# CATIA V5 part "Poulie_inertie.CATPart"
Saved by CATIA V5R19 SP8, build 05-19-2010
Part number: Poulie_inertie
Nomenclature: 69_c
Bounding box of the stored display mesh (mm): x -20 to 42, y -64.996 to 64.996, z -64.996 to 64.996
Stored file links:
  C:\Users\rphgr\Desktop\0_Tapis_TC520B_vitesse\Poulie_inertie.CATPart
  D:\Documents\1_Travail\1 - ac-limoges.fr\ac-limoges.fr\Emmanuel Maynard - STI2D_Turgot\3 - Supports\Tapis de course TC520B\Tapis de course TC520B_Ca\0_Tapis_TC520B.CATProduct
  D:\Documents\1_Travail\1 - ac-limoges.fr\ac-limoges.fr\Emmanuel Maynard - STI2D_Turgot\3 - Supports\Tapis de course TC520B\Tapis de course TC520B_Ca\Rotor.CATPart
  D:\Documents\1_Travail\1 - ac-limoges.fr\ac-limoges.fr\Emmanuel Maynard - STI2D_Turgot\3 - Supports\Tapis de course TC520B\Tapis de course TC520B_Ca\JIS_B_1301_5x5x28_SYMBOL_C_WITHOUT_HOLES_PARALLEL_KEY.CATPart
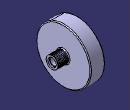
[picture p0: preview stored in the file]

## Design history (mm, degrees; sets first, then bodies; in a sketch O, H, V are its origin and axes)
AxisSystem1: origin (0, 0, 0), X (1, 0, 0), Y (0, 1, 0), Z (0, 0, 1)
Set1
  DatumSurface1 to DatumSurface3
Body1 (main body)
  Sketch1 on ZX plane of AxisSystem1, origin (0, 0, 0), H (0, 0, 1), V (1, 0, 0)
    axis line L1 (0, -2.8084) -> (0, 45.1811)
    point P1 (0, -2.8084)
    line L2 (8, 0) -> (13.25, 0)
    line L3 (13.25, 0) -> (13.25, 6.75)
    line L4 (13.25, 6.75) -> (19.1346, 6.75)
    line L5 (57.5, 7.45) -> (57.5, -20)
    line L6 (57.5, -20) -> (65, -20)
    line L7 (65, -20) -> (65, 15)
    line L8 (65, 15) -> (14.21, 15)
    line L9 (14.21, 15) -> (14.21, 42)
    line L10 (14.21, 42) -> (10, 42)
    line L11 (8, 38.5) -> (8, 0)
    line L12 (10, 42) -> (10, 38.5)
    line L13 (10, 38.5) -> (8, 38.5)
    reference projected line E1 through (0, 0) direction (1, 0) from edge [ZX plane of AxisSystem1 | YZ plane of AxisSystem1]
    line L14 (19.1346, 6.75) -> (19.1346, 7.45)
    line L15 (19.1346, 7.45) -> (57.5, 7.45)
    distance L11 L1 = 8
    distance L3 L1 = 13.25
    distance L2 L4 = 6.75
    distance L15 L4 = 0.7
    distance L6 L2 = 20
    distance L5 L1 = 57.5
    distance L7 L1 = 65
    distance L6 L8 = 35
    distance L9 L1 = 14.21
    distance L10 L8 = 27
    distance L12 L1 = 10
    distance L10 L13 = 3.5
    coincidence: P1 V, L2 E1
    vertical: L1 V, L3 V, L5 V, L7 V, L9 V, L11 V, L12 V, L14 V
    horizontal: L2 H, L4 H, L6 H, L10 H, L8 H, L13 H, L15 H
  Shaft1: profile Sketch1, axis Sketch1.L1, angle 360
  Fillet1: radius 2, on face of Shaft1 from Sketch1.L8; face of Shaft1 from Sketch1.L6
  Sketch2 on ZX plane of AxisSystem1, origin (0, 0, 0), H (0, 0, 1), V (1, 0, 0)
    line L1 (14.1542, 40.076) -> (11.7142, 39.1879)
    line L2 (11.7142, 38.8121) -> (14.1542, 37.924)
    line L3 (14.22, 40.17) -> (14.22, 37.83)
    arc A1 centre (14.12, 37.83) radius 0.1 from (14.1542, 37.924) to (14.22, 37.83) cw
    arc A2 centre (14.12, 40.17) radius 0.1 from (14.1542, 40.076) to (14.22, 40.17) ccw
    point P5 (14.22, 37.83)
    point P6 (14.22, 40.17)
    arc A3 centre (11.7826, 39) radius 0.2 from (11.7142, 39.1879) to (11.7142, 38.8121) ccw
    point P9 (11.7826, 39)
    reference projected line E1 through (0, 0) direction (0, 1) from axis of face of Shaft1 from Sketch1.L9
    reference intersected line E2 through (0, 42) direction (-1, 0) from face of Shaft1 from Sketch1.L10
    radius A1 = 0.1
    radius A2 = 0.1
    radius A3 = 0.2
    distance L3 E1 = 14.22
    distance P9 E2 = 3
    distance P6 P5 = 2.34
    angle L2 L1 = 40
    angle L3 L1 = 70
    vertical: L3 V
    tangency: A1 L2, A1 L3, A2 L1, A2 L3, A3 L1, A3 L2
  Groove1: profile Sketch2, axis axis of face of Shaft1 from Sketch1.L9, angle 360
  RectPattern1: of Groove1, direction 1 instances 9, spacing 2.34, along axis of face of Shaft1 from Sketch1.L9 reversed
  Sketch3 on face of Shaft1 from Sketch1.L10, origin (42, 0, 0), H (0, 1, 0), V (0, 0, 1)
    point P1 (-0.4607, 7.5359)
    line L1 (2.2024, 4.9436) -> (1.8668, 10.4334)
    line L2 (1.8668, 10.4334) -> (-3.1238, 10.1283)
    line L3 (-3.1238, 10.1283) -> (-2.7882, 4.6385)
    line L4 (-2.7882, 4.6385) -> (2.2024, 4.9436)
    reference intersected line E1 through (2.4953, 0.1525) direction (-0.061, 0.9981) from face of DatumSurface1
    reference intersected line E2 through (-0.598, 9.7817) direction (0.9981, 0.061) from face of DatumSurface2
    reference intersected line E3 through (-0.2929, 4.7911) direction (0.9981, 0.061) from face of DatumSurface3
    distance L1 L3 = 5
    distance L2 E2 = 0.5
    equidistance: L1 L3 P1, L2 L4 P1
    coincidence: L1 E1, L4 E3
  Pocket1: profile Sketch3, direction (-1, 0, 0), through (limit type 3)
